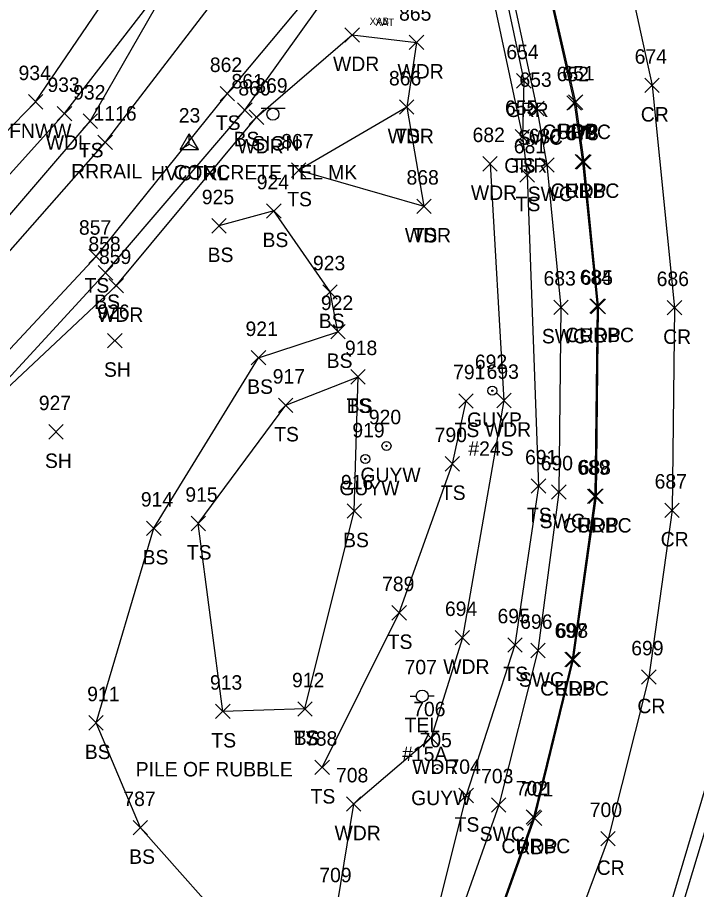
# Model space of a CAD drawing. Extents: x 1764889 to 1767296, y 695936 to 698960.
# Drawn here: x 1766265.6 to 1766359.5, y 696396.7 to 696517.3 of the extents above; entities that cross this region are included whole.
import ezdxf

# ---------------------------------------------------------------- set-up
doc = ezdxf.new("R2010")
doc.units = 0
for name, color, linetype in [('B_A', 7, 'Continuous'), ('C_A', 7, 'Continuous'), ('C_I', 7, 'Continuous'), ('CPSM', 7, 'Continuous'), ('L_A', 7, 'Continuous'), ('L_C', 7, 'Continuous'), ('L_I', 7, 'Continuous'), ('L_TIC', 7, 'Continuous'), ('LAWA', 7, 'Continuous'), ('LELB', 7, 'Continuous'), ('LFNC', 7, 'Continuous'), ('P_A', 7, 'Continuous'), ('P_I', 7, 'Continuous'), ('P_TIC', 7, 'Continuous'), ('PET', 7, 'Continuous'), ('PRC', 7, 'Continuous'), ('R_A', 7, 'Continuous'), ('R_I', 7, 'Continuous'), ('R_TIC', 7, 'Continuous'), ('RC', 7, 'Continuous'), ('RGR', 7, 'Continuous'), ('RR', 7, 'Continuous'), ('RSW', 7, 'Continuous'), ('S_A', 7, 'Continuous'), ('S_C', 7, 'Continuous'), ('S_I', 7, 'Continuous'), ('SSGN', 7, 'Continuous'), ('U_A', 7, 'Continuous'), ('U_C', 7, 'Continuous'), ('U_I', 7, 'Continuous'), ('UP', 7, 'Continuous'), ('UPGW', 7, 'Continuous')]:
    doc.layers.add(name, color=color, linetype=linetype)

msp = doc.modelspace()

# ---------------------------------------------------------------- linework, layer by layer
at = {"layer": 'CPSM'}
for p, q in [((1766288.13, 696499.07), (1766289.38, 696501.23)), ((1766290.63, 696499.07), (1766289.38, 696501.23)), ((1766289.38, 696499.79), (1766289.38, 696501.23)), ((1766288.13, 696499.07), (1766289.38, 696499.79)), ((1766289.38, 696499.79), (1766289.38, 696499.79)), ((1766289.38, 696499.79), (1766290.63, 696499.07)), ((1766288.13, 696499.07), (1766290.63, 696499.07))]:
    msp.add_line(p, q, dxfattribs=at)
at = {"layer": 'L_TIC'}
for points in [[(1766310.89, 696513.91), (1766312.89, 696515.91)], [(1766312.89, 696513.91), (1766310.89, 696515.91)], [(1766319.79, 696512.88), (1766321.79, 696514.88)], [(1766321.79, 696512.88), (1766319.79, 696514.88)], [(1766293.63, 696505.78), (1766295.63, 696507.78)], [(1766295.63, 696505.78), (1766293.63, 696507.78)], [(1766267.13, 696504.66), (1766269.13, 696506.66)], [(1766269.13, 696504.66), (1766267.13, 696506.66)], [(1766318.44, 696503.93), (1766320.44, 696505.93)], [(1766320.44, 696503.93), (1766318.44, 696505.93)], [(1766318.44, 696503.93), (1766320.44, 696505.93)], [(1766320.44, 696503.93), (1766318.44, 696505.93)], [(1766271.12, 696503.03), (1766273.12, 696505.03)], [(1766273.12, 696503.03), (1766271.12, 696505.03)], [(1766296.06, 696503.51), (1766298.06, 696505.51)], [(1766298.06, 696503.51), (1766296.06, 696505.51)], [(1766274.69, 696501.98), (1766276.69, 696503.98)], [(1766276.69, 696501.98), (1766274.69, 696503.98)], [(1766297.66, 696502.53), (1766299.66, 696504.53)], [(1766299.66, 696502.53), (1766297.66, 696504.53)], [(1766334.43, 696499.85), (1766336.43, 696501.85)], [(1766336.43, 696499.85), (1766334.43, 696501.85)], [(1766329.95, 696496.09), (1766331.95, 696498.09)], [(1766331.95, 696496.09), (1766329.95, 696498.09)], [(1766303.5, 696495.21), (1766305.5, 696497.21)], [(1766305.5, 696495.21), (1766303.5, 696497.21)], [(1766335.09, 696494.53), (1766337.09, 696496.53)], [(1766337.09, 696494.53), (1766335.09, 696496.53)], [(1766300.06, 696489.57), (1766302.06, 696491.57)], [(1766302.06, 696489.57), (1766300.06, 696491.57)], [(1766320.82, 696490.21), (1766322.82, 696492.21)], [(1766322.82, 696490.21), (1766320.82, 696492.21)], [(1766320.82, 696490.21), (1766322.82, 696492.21)], [(1766322.82, 696490.21), (1766320.82, 696492.21)], [(1766292.47, 696487.5), (1766294.47, 696489.5)], [(1766294.47, 696487.5), (1766292.47, 696489.5)], [(1766275.48, 696483.28), (1766277.48, 696485.28)], [(1766277.48, 696483.28), (1766275.48, 696485.28)], [(1766276.79, 696481.01), (1766278.79, 696483.01)], [(1766278.79, 696481.01), (1766276.79, 696483.01)], [(1766278.26, 696479.23), (1766280.26, 696481.23)], [(1766280.26, 696479.23), (1766278.26, 696481.23)], [(1766307.83, 696478.36), (1766309.83, 696480.36)], [(1766309.83, 696478.36), (1766307.83, 696480.36)], [(1766308.93, 696472.86), (1766310.93, 696474.86)], [(1766310.93, 696472.86), (1766308.93, 696474.86)], [(1766278.09, 696471.63), (1766280.09, 696473.63)], [(1766280.09, 696471.63), (1766278.09, 696473.63)], [(1766297.94, 696469.27), (1766299.94, 696471.27)], [(1766299.94, 696469.27), (1766297.94, 696471.27)], [(1766311.7, 696466.63), (1766313.7, 696468.63)], [(1766313.7, 696466.63), (1766311.7, 696468.63)], [(1766311.7, 696466.63), (1766313.7, 696468.63)], [(1766313.7, 696466.63), (1766311.7, 696468.63)], [(1766326.64, 696463.29), (1766328.64, 696465.29)], [(1766328.64, 696463.29), (1766326.64, 696465.29)], [(1766331.88, 696463.35), (1766333.88, 696465.35)], [(1766333.88, 696463.35), (1766331.88, 696465.35)], [(1766301.7, 696462.69), (1766303.7, 696464.69)], [(1766303.7, 696462.69), (1766301.7, 696464.69)], [(1766269.94, 696459.02), (1766271.94, 696461.02)], [(1766271.94, 696459.02), (1766269.94, 696461.02)], [(1766324.75, 696454.6), (1766326.75, 696456.6)], [(1766326.75, 696454.6), (1766324.75, 696456.6)], [(1766336.65, 696451.52), (1766338.65, 696453.52)], [(1766338.65, 696451.52), (1766336.65, 696453.52)], [(1766311.19, 696448.06), (1766313.19, 696450.06)], [(1766313.19, 696448.06), (1766311.19, 696450.06)], [(1766289.62, 696446.35), (1766291.62, 696448.35)], [(1766291.62, 696446.35), (1766289.62, 696448.35)], [(1766283.48, 696445.68), (1766285.48, 696447.68)], [(1766285.48, 696445.68), (1766283.48, 696447.68)], [(1766317.4, 696433.99), (1766319.4, 696435.99)], [(1766319.4, 696433.99), (1766317.4, 696435.99)], [(1766326.13, 696430.55), (1766328.13, 696432.55)], [(1766328.13, 696430.55), (1766326.13, 696432.55)], [(1766333.4, 696429.54), (1766335.4, 696431.54)], [(1766335.4, 696429.54), (1766333.4, 696431.54)], [(1766304.37, 696420.69), (1766306.37, 696422.69)], [(1766306.37, 696420.69), (1766304.37, 696422.69)], [(1766304.37, 696420.69), (1766306.37, 696422.69)], [(1766306.37, 696420.69), (1766304.37, 696422.69)], [(1766293.02, 696420.36), (1766295.02, 696422.36)], [(1766295.02, 696420.36), (1766293.02, 696422.36)], [(1766275.49, 696418.77), (1766277.49, 696420.77)], [(1766277.49, 696418.77), (1766275.49, 696420.77)], [(1766321.82, 696416.68), (1766323.82, 696418.68)], [(1766323.82, 696416.68), (1766321.82, 696418.68)], [(1766306.74, 696412.61), (1766308.74, 696414.61)], [(1766308.74, 696412.61), (1766306.74, 696414.61)], [(1766326.65, 696408.72), (1766328.65, 696410.72)], [(1766328.65, 696408.72), (1766326.65, 696410.72)], [(1766311.1, 696407.54), (1766313.1, 696409.54)], [(1766313.1, 696407.54), (1766311.1, 696409.54)], [(1766281.62, 696404.27), (1766283.62, 696406.27)], [(1766283.62, 696404.27), (1766281.62, 696406.27)]]:
    msp.add_lwpolyline(points, dxfattribs=at)
at = {"layer": 'LAWA'}
for points in [[(1766155.54, 696397.9), (1766161.77, 696405.44), (1766181.88, 696420.14), (1766196.06, 696430.7), (1766216.12, 696448.15), (1766224.84, 696455.16), (1766249.96, 696479.46), (1766272.12, 696504.03), (1766288.24, 696524.91), (1766311.88, 696556.72), (1766301.19, 696567.63)], [(1766161.11, 696377.48), (1766185.12, 696394.62), (1766212.55, 696417.35), (1766235.34, 696437.94), (1766256.38, 696458.71), (1766279.26, 696480.23), (1766298.66, 696503.53), (1766311.89, 696514.91), (1766320.79, 696513.88), (1766319.44, 696504.93), (1766321.82, 696491.21)], [(1766330.95, 696497.09), (1766332.88, 696464.35), (1766327.13, 696431.55), (1766322.82, 696417.68), (1766312.1, 696408.54), (1766309.8, 696394.73), (1766296.79, 696389.3)]]:
    msp.add_lwpolyline(points, dxfattribs=at)
at = {"layer": 'LELB'}
for points in [[(1766158.91, 696379.33), (1766183.1, 696397.73), (1766210.95, 696420.2), (1766233.27, 696439.62), (1766253.97, 696460.11), (1766276.48, 696484.28), (1766294.63, 696506.78), (1766322.62, 696540.3)], [(1766256.38, 696458.71), (1766277.79, 696482.01), (1766297.06, 696504.51), (1766322.62, 696540.3)], [(1766328.84, 696531.83), (1766335.43, 696500.85), (1766336.09, 696495.53), (1766337.65, 696452.52), (1766334.4, 696430.54), (1766327.65, 696409.72), (1766321.65, 696385.78), (1766309.99, 696363.08), (1766304.82, 696352.13)], [(1766150.56, 696387.79), (1766167.12, 696399.48), (1766186.95, 696417.34), (1766197.67, 696430.72), (1766217.09, 696445.57), (1766224.84, 696455.16), (1766252.52, 696476.07), (1766275.69, 696502.98), (1766288.24, 696524.91)], [(1766319.44, 696504.93), (1766304.5, 696496.21), (1766321.82, 696491.21)], [(1766296.46, 696353.04), (1766306.9, 696378.88), (1766296.79, 696389.3), (1766282.62, 696405.27), (1766276.49, 696419.77), (1766284.48, 696446.68), (1766298.94, 696470.27), (1766309.93, 696473.86), (1766308.83, 696479.36), (1766301.06, 696490.57), (1766293.47, 696488.5)], [(1766305.37, 696421.69), (1766294.02, 696421.36), (1766290.62, 696447.35), (1766302.7, 696463.69), (1766312.7, 696467.63)], [(1766305.37, 696421.69), (1766312.19, 696449.06), (1766312.7, 696467.63)], [(1766307.74, 696413.61), (1766318.4, 696434.99), (1766325.75, 696455.6), (1766327.64, 696464.29)]]:
    msp.add_lwpolyline(points, dxfattribs=at)
at = {"layer": 'LFNC'}
msp.add_lwpolyline([(1766153.45, 696402.19), (1766162.21, 696408.4), (1766181.16, 696422.27), (1766195.92, 696435.85), (1766221.63, 696458.93), (1766246.19, 696483.05), (1766268.13, 696505.66), (1766282.49, 696526.8), (1766295.32, 696553.41), (1766299.86, 696566.71)], dxfattribs=at)
at = {"layer": 'P_TIC'}
for points in [[(1766352.36, 696506.93), (1766354.36, 696508.93)], [(1766354.36, 696506.93), (1766352.36, 696508.93)], [(1766341.79, 696504.62), (1766343.79, 696506.62)], [(1766343.79, 696504.62), (1766341.79, 696506.62)], [(1766342.93, 696496.35), (1766344.93, 696498.35)], [(1766344.93, 696496.35), (1766342.93, 696498.35)], [(1766344.9, 696476.35), (1766346.9, 696478.35)], [(1766346.9, 696476.35), (1766344.9, 696478.35)], [(1766355.46, 696476.18), (1766357.46, 696478.18)], [(1766357.46, 696476.18), (1766355.46, 696478.18)], [(1766344.61, 696450.13), (1766346.61, 696452.13)], [(1766346.61, 696450.13), (1766344.61, 696452.13)], [(1766355.12, 696448.17), (1766357.12, 696450.17)], [(1766357.12, 696448.17), (1766355.12, 696450.17)], [(1766341.46, 696427.54), (1766343.46, 696429.54)], [(1766343.46, 696427.54), (1766341.46, 696429.54)], [(1766351.9, 696425.11), (1766353.9, 696427.11)], [(1766353.9, 696425.11), (1766351.9, 696427.11)], [(1766336.12, 696405.59), (1766338.12, 696407.59)], [(1766338.12, 696405.59), (1766336.12, 696407.59)], [(1766346.27, 696402.75), (1766348.27, 696404.75)], [(1766348.27, 696402.75), (1766346.27, 696404.75)]]:
    msp.add_lwpolyline(points, dxfattribs=at)
at = {"layer": 'PET'}
msp.add_lwpolyline([(1766331.65, 696550.27), (1766337.19, 696529.87), (1766342.79, 696505.62), (1766343.93, 696497.35), (1766345.9, 696477.35), (1766345.61, 696451.13), (1766342.46, 696428.54), (1766337.12, 696406.59), (1766328.57, 696382.86), (1766317.54, 696359.04), (1766312, 696349.5), (1766322.36, 696346.4), (1766331.24, 696344.36), (1766343.78, 696364.8), (1766353.91, 696387.85), (1766362.68, 696417.29), (1766367.96, 696451.25), (1766367.19, 696487.5)], dxfattribs=at)
at = {"layer": 'PRC'}
msp.add_lwpolyline([(1766338.9, 696564.49), (1766342.21, 696553.11), (1766347.54, 696534.73), (1766353.36, 696507.93), (1766356.46, 696477.18), (1766356.12, 696449.17), (1766352.9, 696426.11), (1766347.27, 696403.75), (1766338.09, 696378.93), (1766326.54, 696354.51), (1766322.36, 696346.4)], dxfattribs=at)
at = {"layer": 'R_TIC'}
for points in [[(1766334.62, 696507.56), (1766336.62, 696509.56)], [(1766336.62, 696507.56), (1766334.62, 696509.56)], [(1766341.58, 696504.51), (1766343.58, 696506.51)], [(1766343.58, 696504.51), (1766341.58, 696506.51)], [(1766336.43, 696503.73), (1766338.43, 696505.73)], [(1766338.43, 696503.73), (1766336.43, 696505.73)], [(1766276.75, 696499.06), (1766278.75, 696501.06)], [(1766278.75, 696499.06), (1766276.75, 696501.06)], [(1766334.43, 696499.85), (1766336.43, 696501.85)], [(1766336.43, 696499.85), (1766334.43, 696501.85)], [(1766337.8, 696495.93), (1766339.8, 696497.93)], [(1766339.8, 696495.93), (1766337.8, 696497.93)], [(1766342.74, 696496.37), (1766344.74, 696498.37)], [(1766344.74, 696496.37), (1766342.74, 696498.37)], [(1766339.76, 696476.25), (1766341.76, 696478.25)], [(1766341.76, 696476.25), (1766339.76, 696478.25)], [(1766344.77, 696476.42), (1766346.77, 696478.42)], [(1766346.77, 696476.42), (1766344.77, 696478.42)], [(1766339.46, 696450.69), (1766341.46, 696452.69)], [(1766341.46, 696450.69), (1766339.46, 696452.69)], [(1766344.44, 696450.09), (1766346.44, 696452.09)], [(1766346.44, 696450.09), (1766344.44, 696452.09)], [(1766336.58, 696428.77), (1766338.58, 696430.77)], [(1766338.58, 696428.77), (1766336.58, 696430.77)], [(1766341.29, 696427.54), (1766343.29, 696429.54)], [(1766343.29, 696427.54), (1766341.29, 696429.54)], [(1766331.16, 696407.41), (1766333.16, 696409.41)], [(1766333.16, 696407.41), (1766331.16, 696409.41)], [(1766335.95, 696405.74), (1766337.95, 696407.74)], [(1766337.95, 696405.74), (1766335.95, 696407.74)]]:
    msp.add_lwpolyline(points, dxfattribs=at)
at = {"layer": 'RC'}
msp.add_lwpolyline([(1766331.2, 696549.96), (1766337.06, 696529.85), (1766342.58, 696505.51), (1766343.74, 696497.37), (1766345.77, 696477.42), (1766345.44, 696451.09), (1766342.29, 696428.54), (1766336.95, 696406.74), (1766328.54, 696383.01), (1766317.22, 696359.23), (1766311.75, 696349.59)], dxfattribs=at)
at = {"layer": 'RGR'}
for points in [[(1766327.44, 696543.71), (1766331.47, 696528.11), (1766335.62, 696508.56), (1766335.43, 696500.85)], [(1766333.29, 696344.42), (1766345.06, 696363.98), (1766355.56, 696387.92), (1766364.33, 696416.92), (1766369.13, 696451.48), (1766368.76, 696487.08)]]:
    msp.add_lwpolyline(points, dxfattribs=at)
at = {"layer": 'RR'}
msp.add_lwpolyline([(1766299.86, 696528.94), (1766277.75, 696500.06), (1766257.52, 696477.14), (1766236.01, 696454.81), (1766202.65, 696425.22), (1766159.82, 696390.23), (1766109.4, 696350.61)], dxfattribs=at)
at = {"layer": 'RSW'}
msp.add_lwpolyline([(1766331.2, 696549.96), (1766327.58, 696544.87), (1766332.36, 696528.32), (1766337.43, 696504.73), (1766338.8, 696496.93), (1766340.76, 696477.25), (1766340.46, 696451.69), (1766337.58, 696429.77), (1766332.16, 696408.41), (1766323.74, 696384.6), (1766312.9, 696361.52), (1766306.49, 696349.77)], dxfattribs=at)
at = {"layer": 'SSGN'}
for p, q in [((1766299.29, 696504.77), (1766302.62, 696504.77)), ((1766300.94, 696503.94), (1766300.94, 696503.94))]:
    msp.add_line(p, q, dxfattribs=at)
msp.add_circle((1766300.94, 696503.94), 0.833, dxfattribs=at)
at = {"layer": 'UP'}
for p, q in [((1766319.92, 696423.48), (1766320.75, 696423.48)), ((1766321.58, 696423.48), (1766321.58, 696423.48)), ((1766323.25, 696423.48), (1766322.41, 696423.48)), ((1766322.41, 696423.48), (1766322.41, 696423.48)), ((1766323.25, 696423.48), (1766323.25, 696423.48))]:
    msp.add_line(p, q, dxfattribs=at)
msp.add_circle((1766321.58, 696423.48), 0.833, dxfattribs=at)
at = {"layer": 'UPGW'}
for centre, radius in [((1766331.27, 696465.7), 0.625), ((1766331.27, 696465.7), 0.0833), ((1766316.64, 696458.07), 0.625), ((1766316.64, 696458.07), 0.0833), ((1766313.72, 696456.25), 0.625), ((1766313.72, 696456.25), 0.0833), ((1766323.65, 696413.39), 0.625), ((1766323.65, 696413.39), 0.0833)]:
    msp.add_circle(centre, radius, dxfattribs=at)

# ---------------------------------------------------------------- texts
at = {"layer": 'B_A'}
for s, p in [('XAB', (1766314.31, 696516.3)), ('XAT', (1766315.1, 696516.16))]:
    msp.add_text(s, height=1, dxfattribs=at).set_placement(p)
at = {"layer": 'C_A'}
msp.add_text('HVCTRL', height=2, dxfattribs=at).set_placement((1766284.08, 696494.79))
at = {"layer": 'C_I'}
msp.add_text('23', height=2, dxfattribs=at).set_placement((1766287.92, 696502.79))
at = {"layer": 'L_A'}
for s, p in [('WDR', (1766309.25, 696509.91)), ('WDR', (1766318.16, 696508.88)), ('TS', (1766293.04, 696501.78)), ('FNWW', (1766264.47, 696500.66)), ('WDL', (1766269.54, 696499.03)), ('BS', (1766295.5, 696499.51)), ('WDR', (1766316.8, 696499.93)), ('TS', (1766317.85, 696499.93)), ('TS', (1766274.1, 696497.98)), ('WDR', (1766296.02, 696498.53)), ('TS', (1766333.84, 696495.85)), ('WDR', (1766328.31, 696492.09)), ('TS', (1766302.91, 696491.21)), ('TS', (1766334.5, 696490.53)), ('WDR', (1766319.18, 696486.21)), ('TS', (1766320.23, 696486.21)), ('BS', (1766299.5, 696485.57)), ('BS', (1766291.91, 696483.5)), ('TS', (1766274.89, 696479.28)), ('BS', (1766276.23, 696477.01)), ('WDR', (1766276.63, 696475.23)), ('BS', (1766307.28, 696474.36)), ('BS', (1766308.37, 696468.86)), ('SH', (1766277.58, 696467.63)), ('BS', (1766297.38, 696465.27)), ('TS', (1766311.11, 696462.63)), ('BS', (1766311.14, 696462.63)), ('TS', (1766326.05, 696459.29)), ('WDR', (1766330.25, 696459.35)), ('TS', (1766301.11, 696458.69)), ('SH', (1766269.42, 696455.02)), ('TS', (1766324.16, 696450.6)), ('TS', (1766336.05, 696447.52)), ('BS', (1766310.64, 696444.06)), ('TS', (1766289.03, 696442.35)), ('BS', (1766282.92, 696441.68)), ('TS', (1766316.81, 696429.99)), ('WDR', (1766324.49, 696426.55)), ('TS', (1766332.8, 696425.54)), ('TS', (1766292.43, 696416.36)), ('TS', (1766303.78, 696416.69)), ('BS', (1766303.81, 696416.69)), ('BS', (1766274.93, 696414.77)), ('WDR', (1766320.19, 696412.68)), ('TS', (1766306.15, 696408.61)), ('TS', (1766326.06, 696404.72)), ('WDR', (1766309.46, 696403.54)), ('BS', (1766281.06, 696400.27))]:
    msp.add_text(s, height=2, dxfattribs=at).set_placement(p)
at = {"layer": 'L_C'}
msp.add_text('PILE OF RUBBLE', height=2, dxfattribs=at).set_placement((1766281.97, 696412.36))
at = {"layer": 'L_I'}
for s, p in [('865', (1766318.38, 696516.88)), ('934', (1766265.77, 696508.66)), ('862', (1766292.22, 696509.78)), ('861', (1766295.21, 696507.51)), ('866', (1766316.98, 696507.93)), ('866', (1766316.98, 696507.93)), ('933', (1766269.76, 696507.03)), ('860', (1766296.16, 696506.53)), ('932', (1766273.32, 696505.98)), ('655', (1766333.02, 696503.85)), ('867', (1766302.09, 696499.21)), ('682', (1766328.54, 696500.09)), ('681', (1766334.24, 696498.53)), ('868', (1766319.41, 696494.21)), ('868', (1766319.41, 696494.21)), ('924', (1766298.7, 696493.57)), ('925', (1766291.11, 696491.5)), ('857', (1766274.12, 696487.28)), ('858', (1766275.43, 696485.01)), ('859', (1766276.89, 696483.23)), ('923', (1766306.47, 696482.36)), ('922', (1766307.57, 696476.86)), ('926', (1766276.67, 696475.63)), ('921', (1766297.15, 696473.27)), ('918', (1766310.9, 696470.63)), ('918', (1766310.9, 696470.63)), ('917', (1766300.91, 696466.69)), ('791', (1766325.85, 696467.29)), ('693', (1766330.48, 696467.35)), ('927', (1766268.57, 696463.02)), ('790', (1766323.3, 696458.6)), ('691', (1766335.8, 696455.52)), ('916', (1766310.34, 696452.06)), ('914', (1766282.68, 696449.68)), ('915', (1766288.83, 696450.35)), ('789', (1766316.03, 696437.99)), ('694', (1766324.72, 696434.55)), ('695', (1766331.99, 696433.54)), ('913', (1766292.23, 696424.36)), ('912', (1766303.58, 696424.69)), ('912', (1766303.58, 696424.69)), ('911', (1766275.26, 696422.77)), ('706', (1766320.33, 696420.68)), ('788', (1766305.38, 696416.61)), ('704', (1766325.21, 696412.72)), ('708', (1766309.66, 696411.54)), ('787', (1766280.26, 696408.27)), ('709', (1766307.35, 696397.73))]:
    msp.add_text(s, height=2, dxfattribs=at).set_placement(p)
at = {"layer": 'P_A'}
for s, p in [('CR', (1766351.8, 696502.93)), ('RDP', (1766340.28, 696500.62)), ('RDP', (1766341.41, 696492.35)), ('RDP', (1766343.38, 696472.35)), ('CR', (1766354.89, 696472.18)), ('RDP', (1766343.1, 696446.13)), ('CR', (1766354.55, 696444.17)), ('RDP', (1766339.94, 696423.54)), ('CR', (1766351.33, 696421.11)), ('RDP', (1766334.61, 696401.59)), ('CR', (1766345.7, 696398.75))]:
    msp.add_text(s, height=2, dxfattribs=at).set_placement(p)
at = {"layer": 'P_I'}
for s, p in [('674', (1766350.95, 696510.93)), ('651', (1766340.95, 696508.62)), ('678', (1766341.52, 696500.35)), ('685', (1766343.49, 696480.35)), ('686', (1766353.99, 696480.18)), ('688', (1766343.21, 696454.13)), ('687', (1766353.71, 696452.17)), ('698', (1766340.05, 696431.54)), ('699', (1766350.48, 696429.11)), ('701', (1766335.25, 696409.59)), ('700', (1766344.74, 696406.75))]:
    msp.add_text(s, height=2, dxfattribs=at).set_placement(p)
at = {"layer": 'R_A'}
for s, p in [('GRR', (1766333.11, 696503.56)), ('CURBC', (1766338.16, 696500.51)), ('SWC', (1766334.79, 696499.73)), ('GRR', (1766332.92, 696495.85)), ('RRRAIL', (1766273.05, 696495.06)), ('SWC', (1766336.16, 696491.93)), ('CURBC', (1766339.32, 696492.37)), ('CURBC', (1766341.35, 696472.42)), ('SWC', (1766338.12, 696472.25)), ('SWC', (1766337.82, 696446.69)), ('CURBC', (1766341.02, 696446.09)), ('SWC', (1766334.94, 696424.77)), ('CURBC', (1766337.88, 696423.54)), ('SWC', (1766329.52, 696403.41)), ('CURBC', (1766332.53, 696401.74))]:
    msp.add_text(s, height=2, dxfattribs=at).set_placement(p)
at = {"layer": 'R_I'}
for s, p in [('654', (1766333.21, 696511.56)), ('653', (1766335.02, 696507.73)), ('652', (1766340.17, 696508.51)), ('655', (1766333.02, 696503.85)), ('1116', (1766276.14, 696503.06)), ('679', (1766341.32, 696500.37)), ('680', (1766336.3, 696499.93)), ('683', (1766338.35, 696480.25)), ('684', (1766343.36, 696480.42)), ('690', (1766337.96, 696454.69)), ('689', (1766343.02, 696454.09)), ('696', (1766335.12, 696432.77)), ('697', (1766339.88, 696431.54)), ('703', (1766329.72, 696411.41)), ('702', (1766334.51, 696409.74))]:
    msp.add_text(s, height=2, dxfattribs=at).set_placement(p)
at = {"layer": 'S_A'}
msp.add_text('SIGN', height=2, dxfattribs=at).set_placement((1766298.07, 696498.92))
at = {"layer": 'S_C'}
msp.add_text('CONCRETE TEL MK', height=2, dxfattribs=at).set_placement((1766287.18, 696494.92))
at = {"layer": 'S_I'}
msp.add_text('869', height=2, dxfattribs=at).set_placement((1766298.5, 696506.92))
at = {"layer": 'U_A'}
for s, p in [('GUYP', (1766327.78, 696460.7)), ('GUYW', (1766313.04, 696453.07)), ('GUYW', (1766310.12, 696451.25)), ('TEL', (1766319.14, 696418.48)), ('GUYW', (1766320.05, 696408.39))]:
    msp.add_text(s, height=2, dxfattribs=at).set_placement(p)
at = {"layer": 'U_C'}
for s, p in [('#24S', (1766327.96, 696456.7)), ('#15A', (1766318.8, 696414.48))]:
    msp.add_text(s, height=2, dxfattribs=at).set_placement(p)
at = {"layer": 'U_I'}
for s, p in [('692', (1766328.86, 696468.7)), ('920', (1766314.2, 696461.07)), ('919', (1766311.92, 696459.25)), ('707', (1766319.14, 696426.48)), ('705', (1766321.21, 696416.39))]:
    msp.add_text(s, height=2, dxfattribs=at).set_placement(p)

doc.saveas('drawing.dxf')
